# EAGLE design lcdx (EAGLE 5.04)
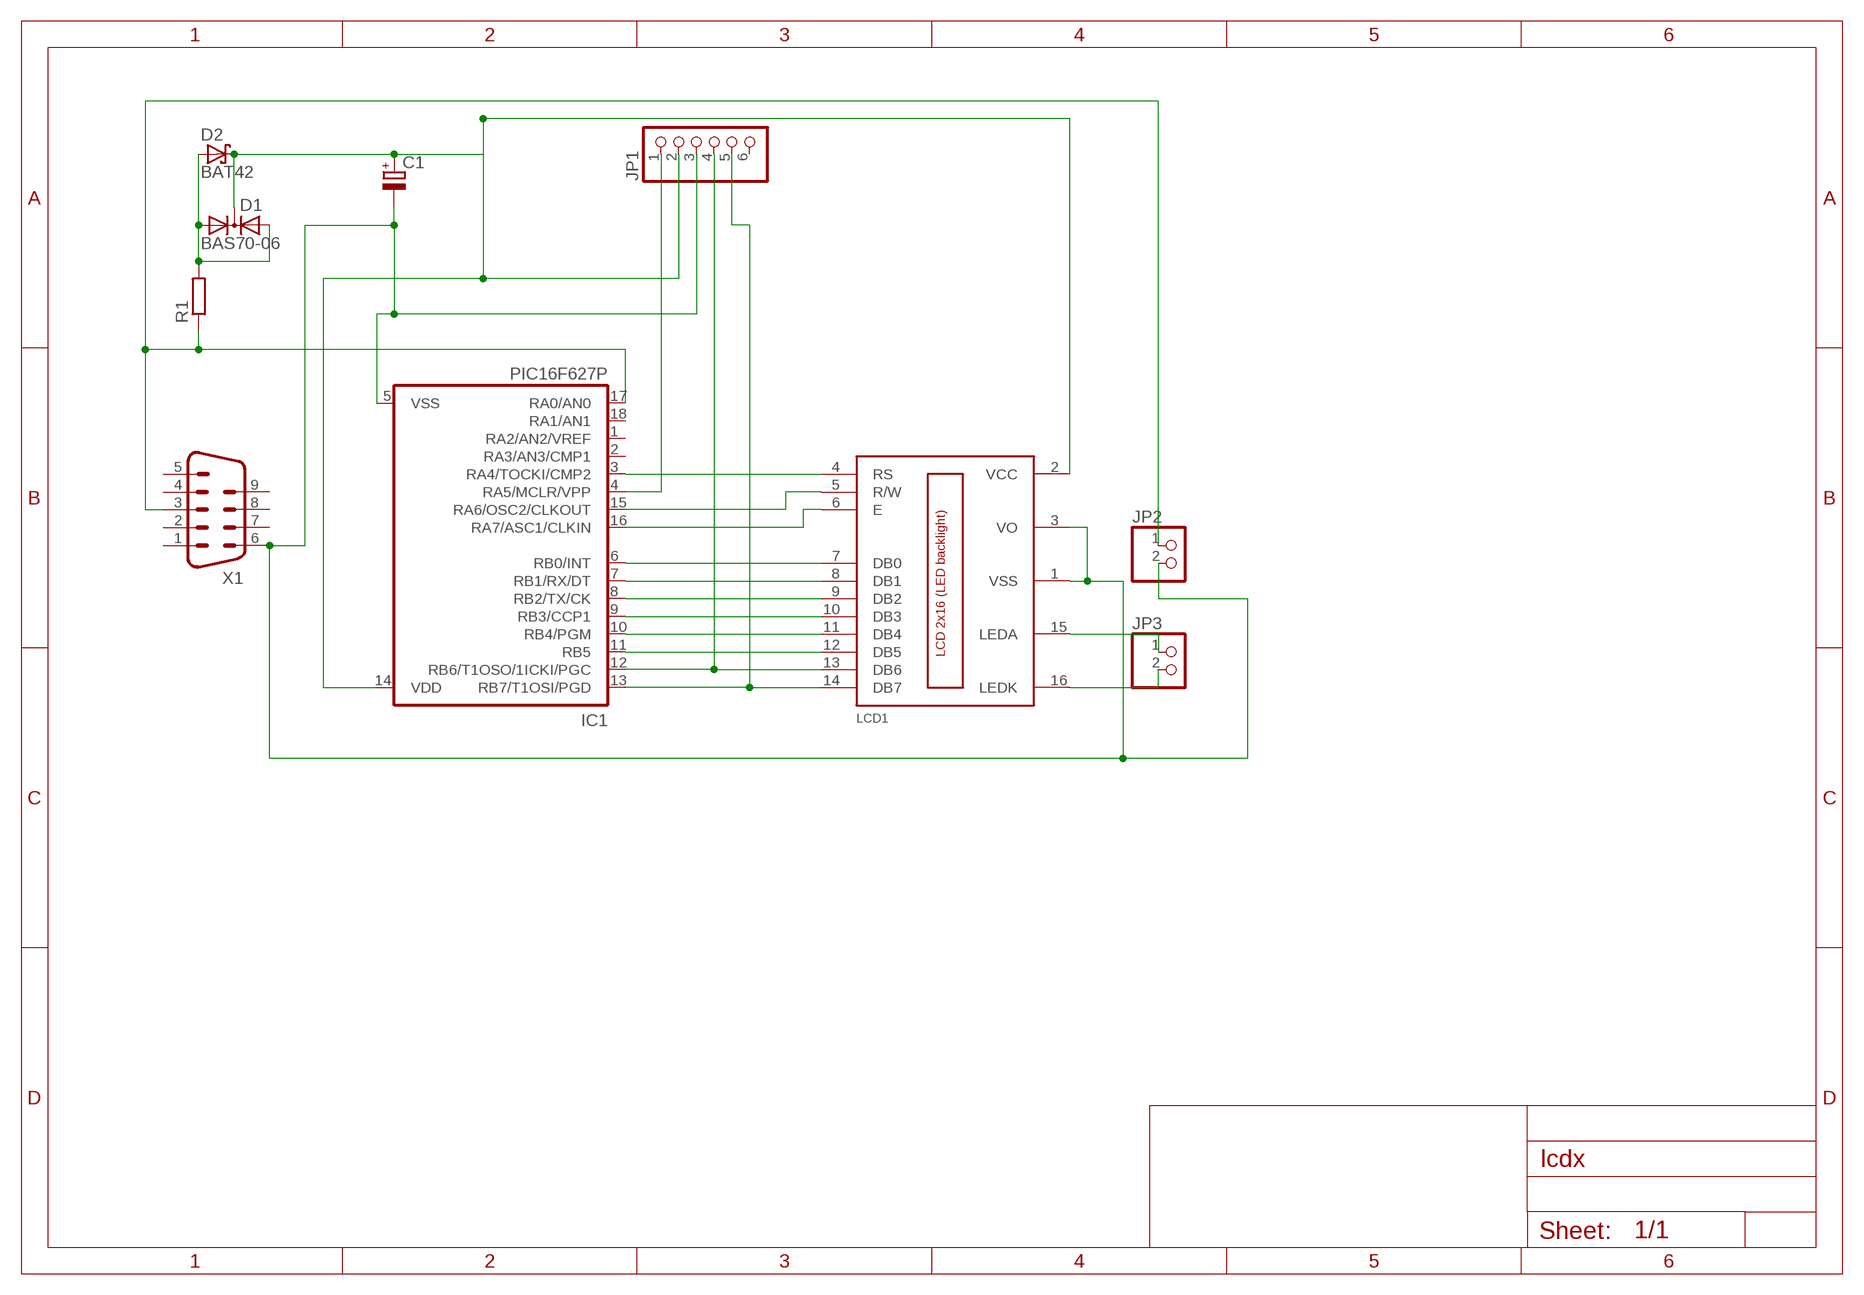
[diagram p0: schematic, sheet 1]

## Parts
C1  CPOL-EUE2.5-6  [E2,5-6]
D1  BAS70-06  [SOT23]
D2  BAT42  [DO35-10]
IC1  PIC16F627P  [DIL18]
JP1  PINHD-1X6  [1X06]
JP2  PINHD-1X2  [1X02]
JP3  PINHD-1X2  [1X02]
LCD1  LCD_2X16  [HY-1602F]
R1  R-EU_0204/2V  [0204V]
X1  M09HP  [M09HP]

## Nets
N$1: IC1.4(RA5/MCLR/VPP) JP1.1
N$2: IC1.12(RB6/T1OSO/1ICKI/PGC) JP1.4 LCD1.13(DB6)
N$3: IC1.13(RB7/T1OSI/PGD) JP1.5 LCD1.14(DB7)
N$4: C1.- IC1.5(VSS) JP1.3 JP2.2 LCD1.1(VSS) LCD1.3(VO) X1.6
N$5: C1.+ D1.3(C) D2.C IC1.14(VDD) JP1.2 LCD1.2(VCC)
N$6: IC1.11(RB5) LCD1.12(DB5)
N$7: IC1.10(RB4/PGM) LCD1.11(DB4)
N$8: IC1.9(RB3/CCP1) LCD1.10(DB3)
N$9: IC1.8(RB2/TX/CK) LCD1.9(DB2)
N$10: IC1.7(RB1/RX/DT) LCD1.8(DB1)
N$11: IC1.6(RB0/INT) LCD1.7(DB0)
N$12: IC1.16(RA7/ASC1/CLKIN) LCD1.6(E)
N$13: IC1.15(RA6/OSC2/CLKOUT) LCD1.5(R/W)
N$14: IC1.3(RA4/TOCKI/CMP2) LCD1.4(RS)
N$17: IC1.17(RA0/AN0) JP2.1 R1.1 X1.3
N$19: D1.1(A1) D1.2(A2) D2.A R1.2
N$22: JP3.2 LCD1.16(LEDK)
N$23: JP3.1 LCD1.15(LEDA)
Unconnected: IC1.1(RA2/AN2/VREF) IC1.2(RA3/AN3/CMP1) IC1.18(RA1/AN1) JP1.6 X1.1 X1.2 X1.4 X1.5 X1.7 X1.8 X1.9

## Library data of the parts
C1 = rcl-2:CPOL-EU: POLARIZED CAPACITOR, European symbol
D1 = diode-1:BAS70-06: Silicon Schottky Diodes General-purpose diode for high-speed switching
D2 = diode-1:BAT42: DIODE
IC1 = microchip:PIC16*F62: FLASH-Based 8-Bit CMOS Microcontroller Source: http://ww1.microchip.com/downloads/en/DeviceDoc/40300C.pdf
JP1 = pinhead:PINHD-1X6: PIN HEADER
JP2 JP3 = pinhead:PINHD-1X2: PIN HEADER
LCD1 = lcd_2x16_led_backlight:LCD_2X16
R1 = rcl-2:R-EU_: RESISTOR, European symbol
X1 = con-subd:M09: SUB-D

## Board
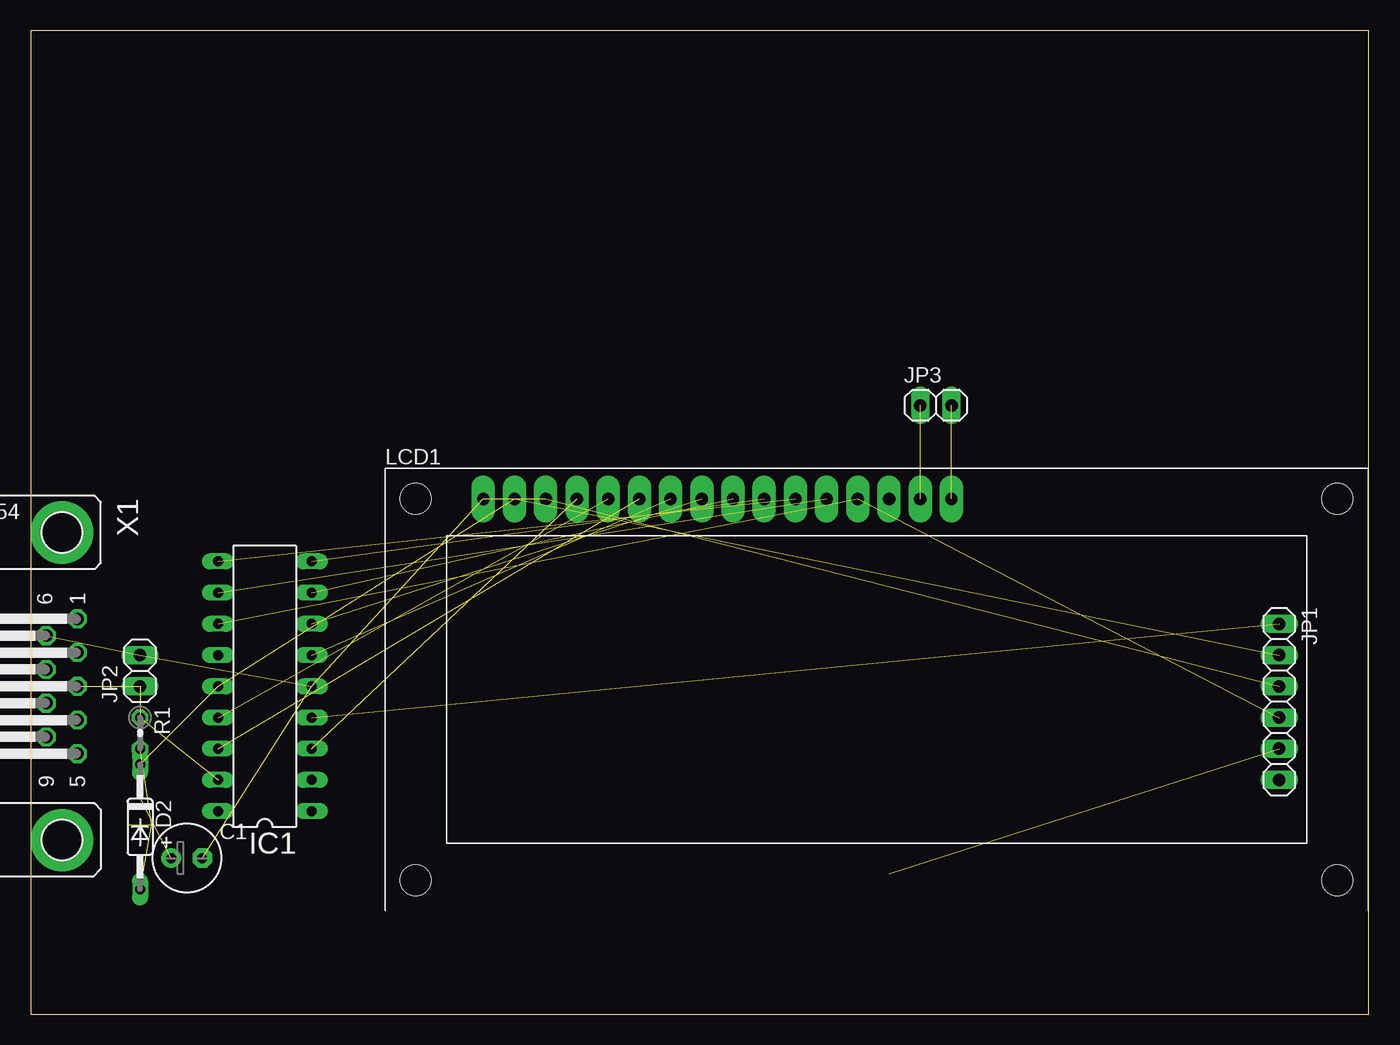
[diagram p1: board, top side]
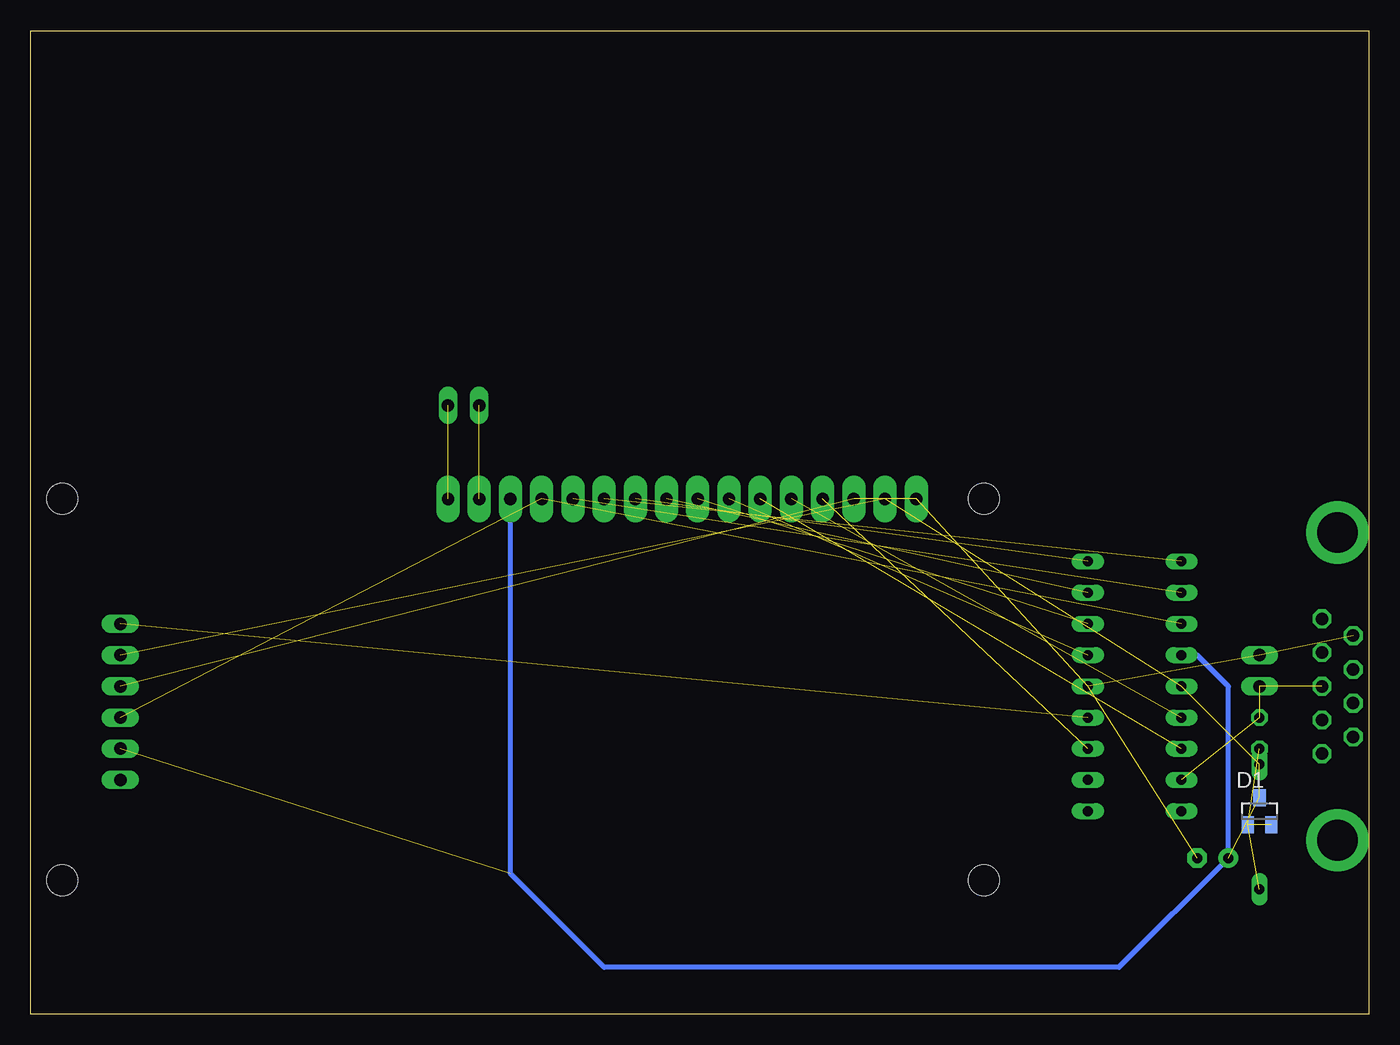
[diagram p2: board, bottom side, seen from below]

Size 108.89 x 80 mm. Coordinates in mm from the lower left corner, seen from the top.
Outline: 0,0 108.89,0 108.89,80 0,80 0,0
Copper layers (1*16): Top 0.035mm / dielectric 1.5mm / Bottom 0.035mm
Design rules "default": minimum track width 10mil, minimum drill 24mil, track to track 8mil, track to pad 8mil, pad to pad 8mil, via to via 8mil, smd to smd 8mil, copper to edge 40mil, drill to drill 8mil, minimum pad ring 10mil, minimum via ring 8mil, stop-mask expansion 4mil, vias tented up to drill 0mil, thermal gap 10mil

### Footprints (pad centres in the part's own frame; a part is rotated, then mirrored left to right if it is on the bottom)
E2,5-6 = drill 0.813 pad 1.6 round: + -1.27,0 | drill 0.813 pad 1.6 octagon: - 1.27,0
SOT23 = smd 1 x 1.4: 1 -0.95,-1.1; 2 0.95,-1.1; 3 0,1.1
DO35-10 = drill 0.813 long: A 5.08,0; C -5.08,0
DIL18 = drill 0.813 long: 1 -10.16,-3.81; 2 -7.62,-3.81; 3 -5.08,-3.81; 4 -2.54,-3.81; 5 0,-3.81; 6 2.54,-3.81; 7 5.08,-3.81; 8 7.62,-3.81; 9 10.16,-3.81; 10 10.16,3.81; 11 7.62,3.81; 12 5.08,3.81; 13 2.54,3.81; 14 0,3.81; 15 -2.54,3.81; 16 -5.08,3.81; 17 -7.62,3.81; 18 -10.16,3.81
1X06 = drill 1.016 long: 1 -6.35,0; 2 -3.81,0; 3 -1.27,0; 4 1.27,0; 5 3.81,0; 6 6.35,0
1X02 = drill 1.016 long: 1 -1.27,0; 2 1.27,0
HY-1602F = drill 1 pad 1.93 long: 1 2.54,0; 2 5.08,0; 3 7.62,0; 4 10.16,0; 5 12.7,0; 6 15.24,0; 7 17.78,0; 8 20.32,0; 9 22.86,0; 10 25.4,0; 11 27.94,0; 12 30.48,0; 13 33.02,0; 14 35.56,0; 15 38.1,0; 16 40.64,0 | hole 2.5: -2.96,0; 72.04,0; -2.96,-31; 72.04,-31
0204V = drill 0.813 octagon: 1 -1.27,0; 2 1.27,0
M09HP = drill 1.016 octagon: 1 -5.486,1.27; 2 -2.743,1.27; 3 0,1.27; 4 2.743,1.27; 5 5.486,1.27; 6 -4.115,-1.27; 7 -1.372,-1.27; 8 1.372,-1.27; 9 4.115,-1.27 | drill 3.302 pad 5.08 round: G1 -12.522,0; G2 12.522,0

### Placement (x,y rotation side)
C1  12.7,12.7 0 top
D1  8.89,16.51 0 bottom
D2  8.89,15.24 270 top
IC1  19.05,26.67 90 top
JP1  101.6,25.4 270 top
JP2  8.89,27.94 90 top
JP3  73.66,49.53 0 top
LCD1  34.29,41.91 0 top
R1  8.89,22.86 270 top
X1  2.54,26.67 270 top

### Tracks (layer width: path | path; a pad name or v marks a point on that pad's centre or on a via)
N$1  (1 unrouted)
N$2  (2 unrouted)
N$3  (1 unrouted)
  Bottom 0.406: LCD1.14 69.85,11.43 62.23,3.81 20.32,3.81 11.43,12.7 11.43,26.67 13.97,29.21 IC1.13
N$4  (6 unrouted)
N$5  (5 unrouted)
N$6  (1 unrouted)
N$7  (1 unrouted)
N$8  (1 unrouted)
N$9  (1 unrouted)
N$10  (1 unrouted)
N$11  (1 unrouted)
N$12  (1 unrouted)
N$13  (1 unrouted)
N$14  (1 unrouted)
N$17  (3 unrouted)
N$19  (3 unrouted)
N$22  (1 unrouted)
N$23  (1 unrouted)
